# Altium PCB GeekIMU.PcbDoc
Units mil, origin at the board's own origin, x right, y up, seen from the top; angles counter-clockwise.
Board outline 1150.03 x 1090.03 mil, 2 copper layers (Top Layer, Bottom Layer); 40 components, 56 nets, 192 pads, 87 vias.
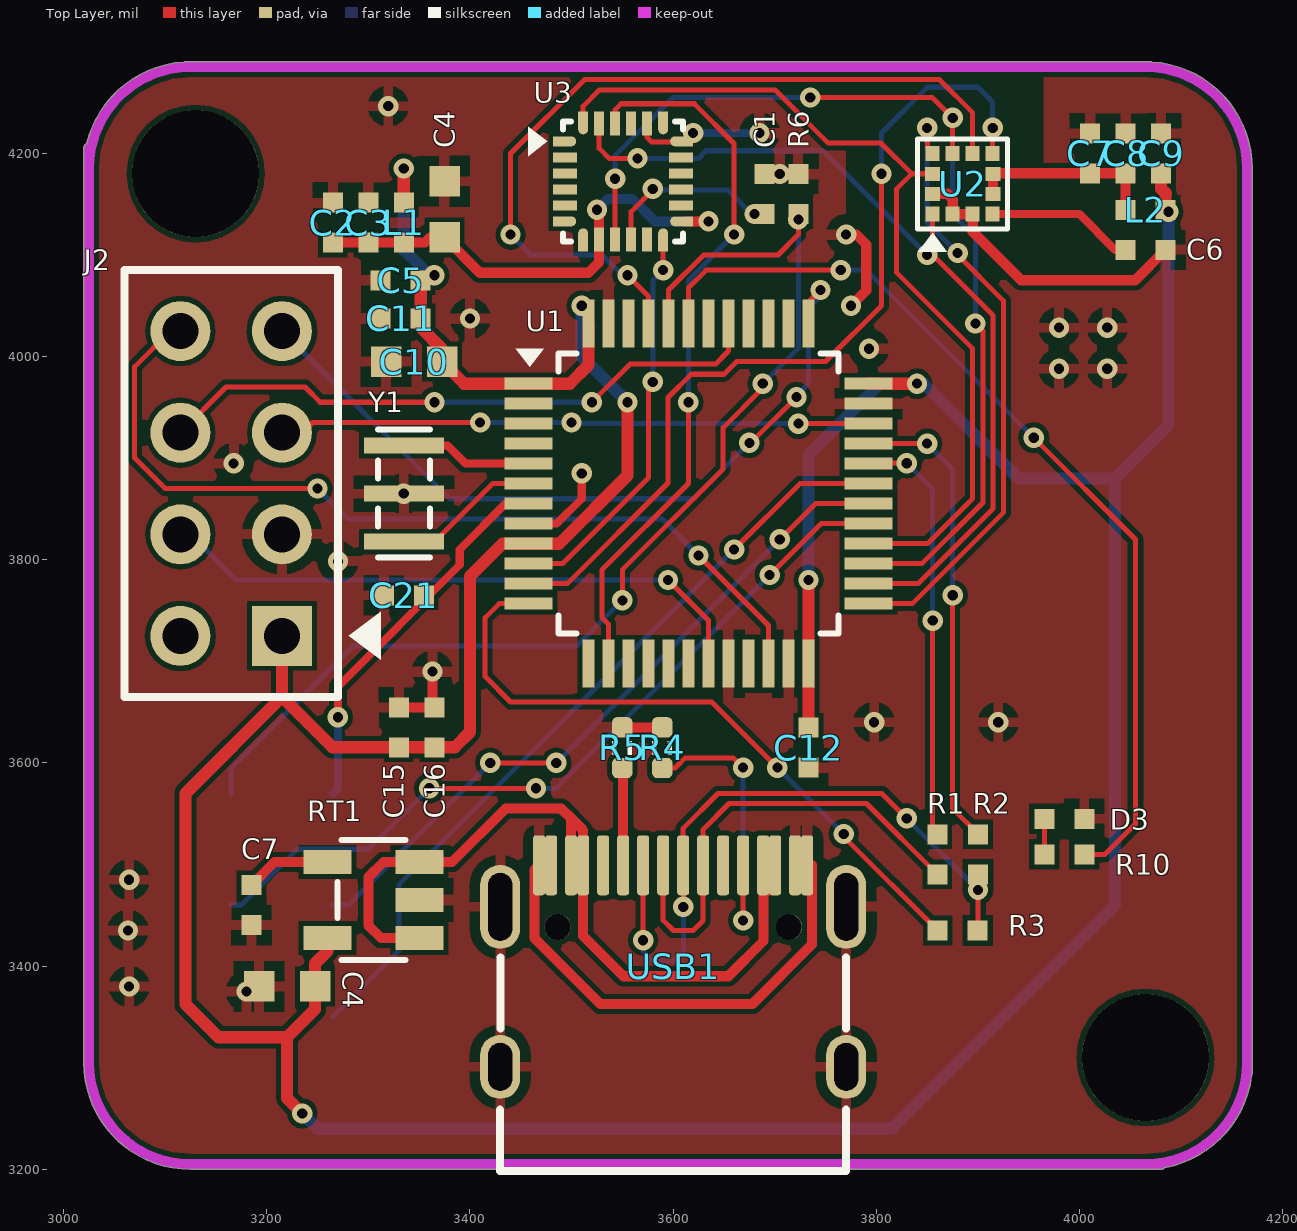
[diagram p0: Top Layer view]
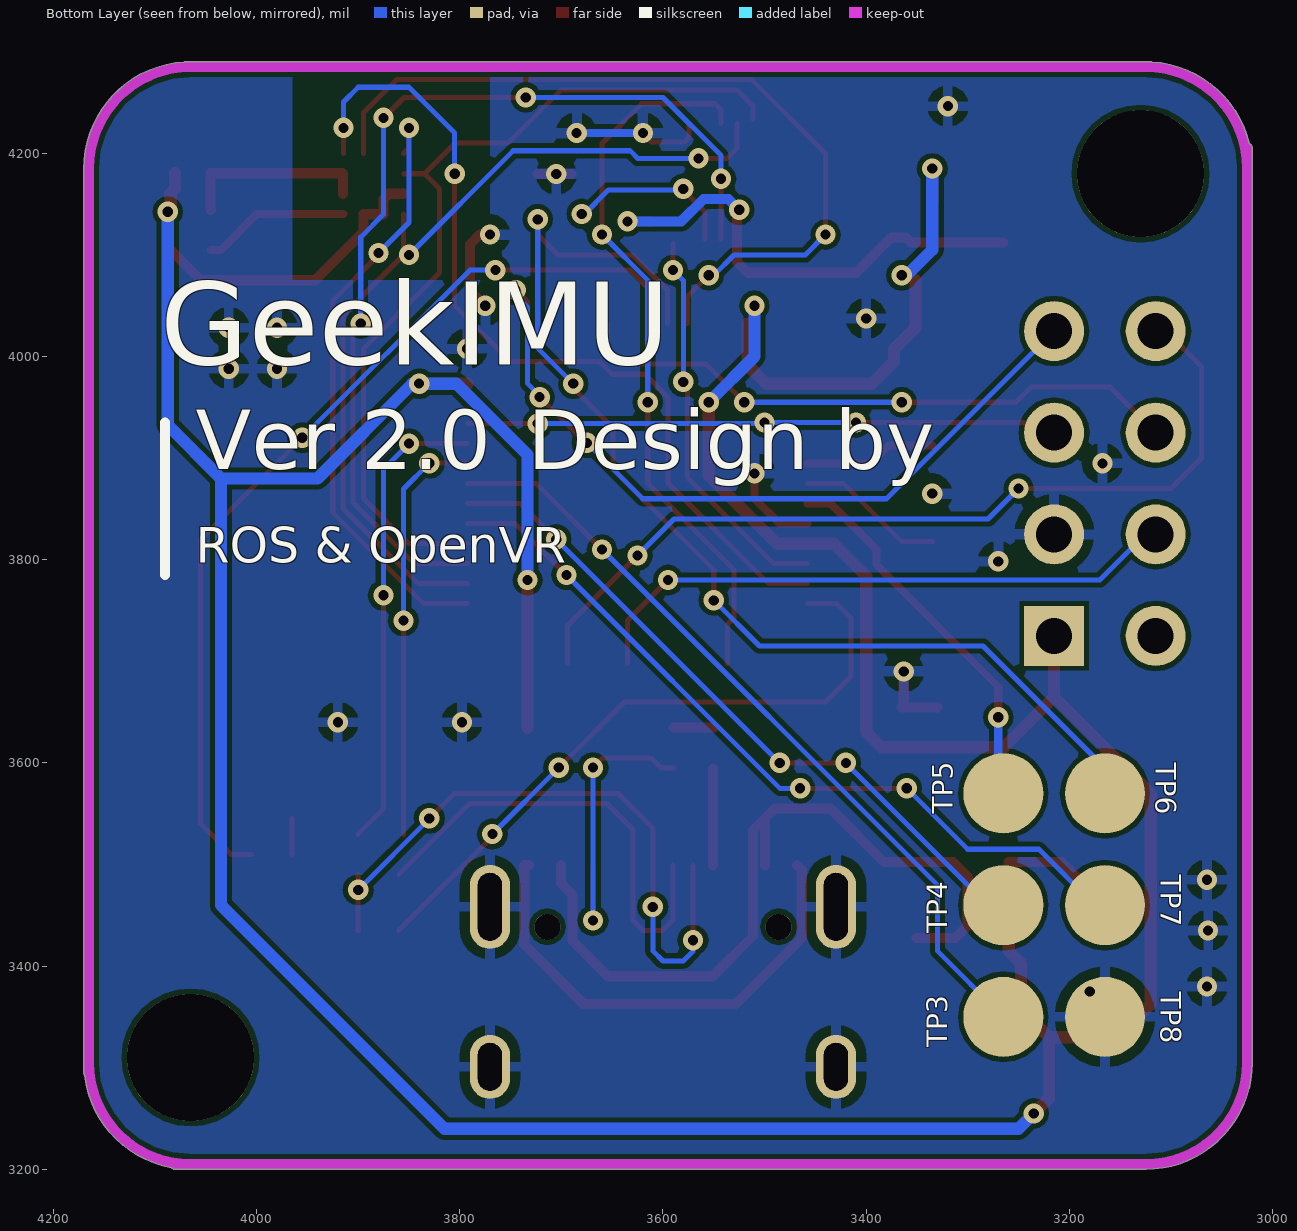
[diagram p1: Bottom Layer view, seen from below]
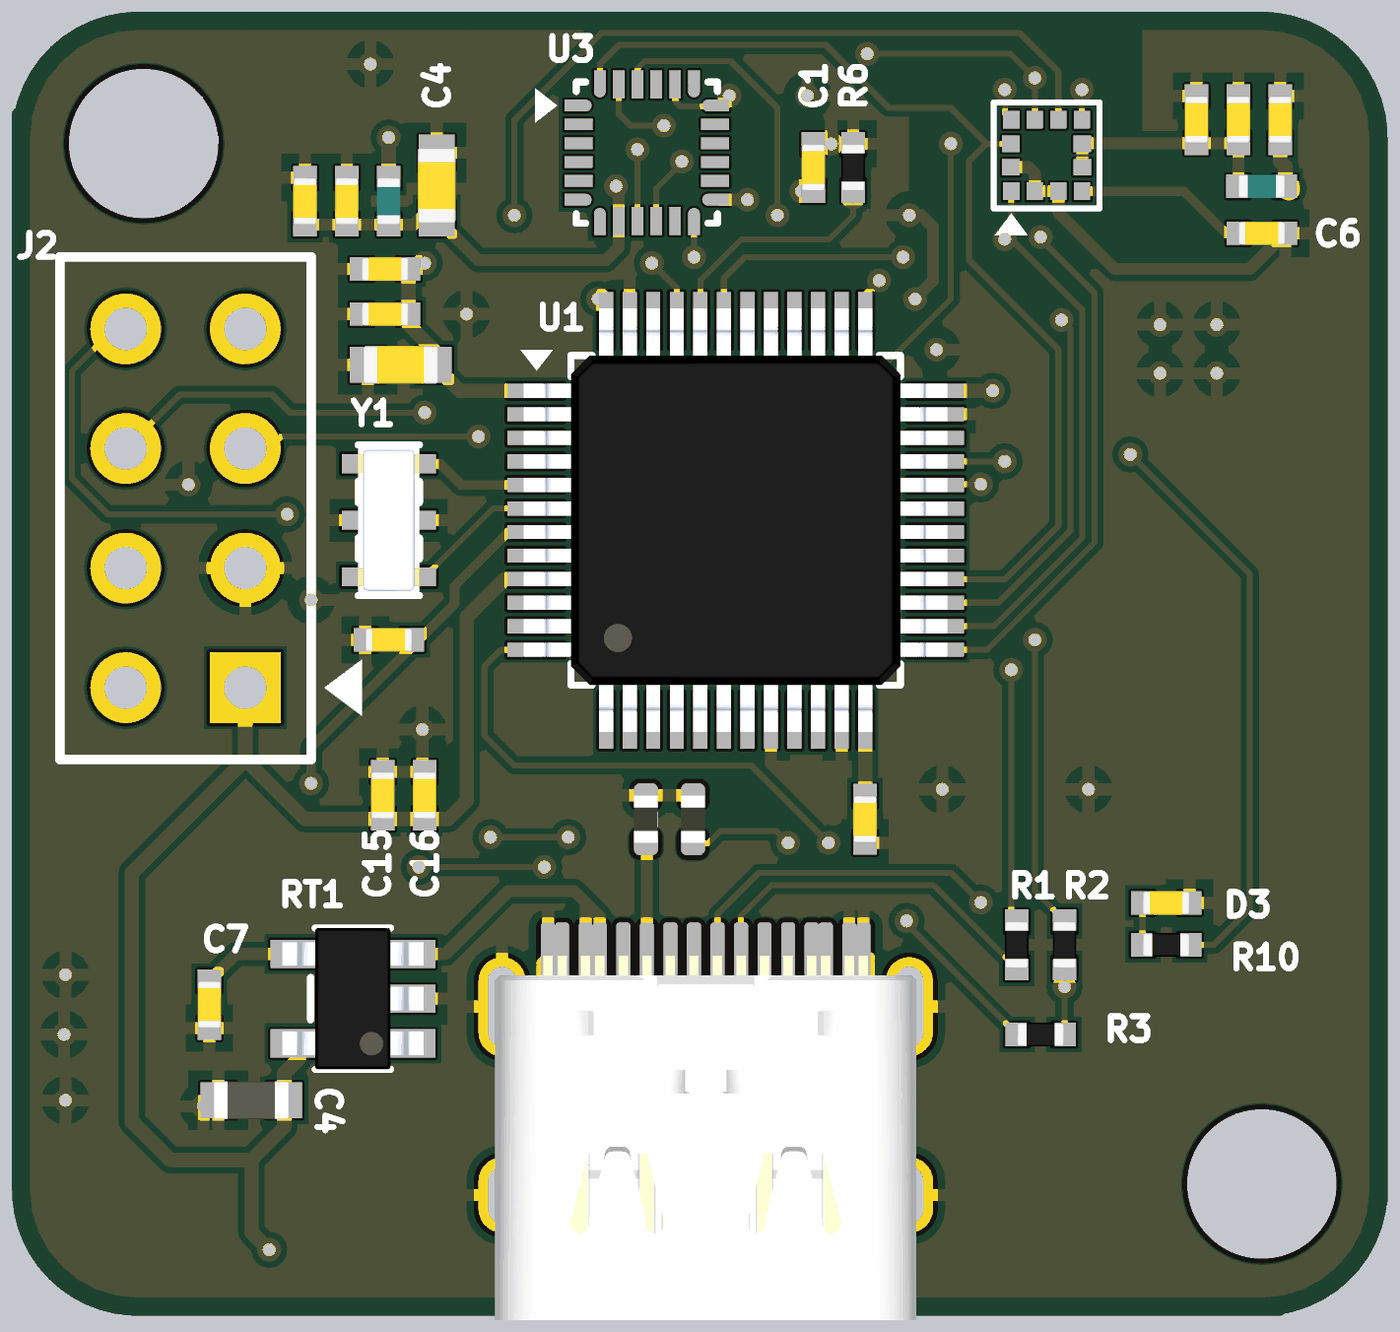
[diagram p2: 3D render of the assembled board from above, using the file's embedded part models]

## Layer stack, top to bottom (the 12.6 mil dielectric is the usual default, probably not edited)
Top Solder: solder mask 0.4, Solder Resist, Dk 3.5
Top Layer: signal copper 1.4
Dielectric1: dielectric 12.6, FR-4, Dk 4.8
Bottom Layer: signal copper 1.4
Bottom Solder: solder mask 0.4, Solder Resist, Dk 3.5

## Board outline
3019.99,3305 3019.99,4205 cw(c3025,4205) 3022.9,4209.55 cw(c3125,4185) 3118.62,4289.82 cw(c3120,4285) 3120,4290.02 4070,4290.02 cw(c4070,4285) 4071.38,4289.82 cw(c4065,4185) 4170.02,4185 4170.02,3295 cw(c4165,3295) 4169.25,3292.34 cw(c4065,3305) 4083.75,3201.67 cw(c4080,3205) 4080,3199.99 3125,3199.99 cw(c3125,3305)

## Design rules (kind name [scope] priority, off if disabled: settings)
Clearance [All] p1: gap=5 ignorepadtopadclearanceinfootprint=FALSE except(0: Arc-Hole Track-Hole SMDPad-Hole THPad-Hole Via-Hole Fill-Hole Poly-Hole Region-Hole Text-Hole)
DiffPairsRouting [All] p1: maxlimit=20 minlimit=5 mostfreqgap=5 toplayer_minwidth=15 toplayer_maxwidth=15 toplayer_prefwidth=15 bottomlayer_minwidth=15 bottomlayer_maxwidth=15 bottomlayer_prefwidth=15 maxuncoupledlength=500
FabricationTestpoint [(IsPad And (OnTopLayer Or OnBottomLayer))] p1: side=3 testpointundercomponent=TRUE minsize=40 maxsize=100 preferedsize=60 minholesize=0 maxholesize=40 preferedholesize=32 testpointgrid=1 allowsidetop=TRUE allowsidebottom=TRUE usegrid=TRUE gridtolerance=0.01
HoleSize [All] p1: absolutevalues=TRUE maxlimit=135 minlimit=1 maxpercent=80.000 minpercent=20.000
MinimumSolderMaskSliver [All] p1: minsoldermaskwidth=1
PolygonConnect [All] p1: connectstyle=Relief reliefconductorwidth=10 reliefentries=4 polygonreliefangle="90 Angle" airgapwidth=10
RoutingVias [All] p1: holewidth=8 width=18 viastyle="Through Hole" minholewidth=8 minwidth=8 maxholewidth=50 maxwidth=50
SilkToSilkClearance [All] p1: silktosilkclearance=0
SilkToSolderMaskClearance SilkscreenOverComponentPads [IsPad] p1: minsilkscreentomaskgap=0 clearancetoexposedcopper=TRUE
SolderMaskExpansion [All] p1: expansion=4
Width [All] p1: maxlimit=30 minlimit=5 preferedwidth=10 minimp=50.000000 maximp=50.000000 favimp=50.000000
24 further rules are at their usual default settings.

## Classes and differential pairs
component class MCU: C10 C11 C12 C15 C16 C21 D3 R6 R10 TP3 TP4 TP5 TP6 TP7 U1 Y1
component class Power: C4 C7 RT1
component class Sensor: C1 C2 C3 C4 C5 C6 C7 C8 C9 L1 L2 U2 U3
component class USB: R1 R2 R3 R4 R5 TP8 USB1

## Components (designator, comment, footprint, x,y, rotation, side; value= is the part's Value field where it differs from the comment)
C1 "0.1uF" CAP_CERAMIC_0402 3690,4160 r90 top
C2 "0.01uF" CAP_CERAMIC_0402 3265,4131.81 r90 top
C3 "0.1uF" CAP_CERAMIC_0402 3299.95,4131.81 r90 top
C4 "Cap" RESISTOR_0603 3220,3380 r0 top value=10uf
C4 "10uF" CAP_CERAMIC_0603 3375,4144.84 r90 top
C5 "0.1uF" CAP_CERAMIC_0402 3331.86,4075 r180 top
C6 "0.1uF" CAP_CERAMIC_0402 4065,4105 r0 top
C7 "Cap" CAP_CERAMIC_0402 3185,3460 r90 top value=0.1uf
C7 "0.1uF" CAP_CERAMIC_0402 4010.31,4200 r90 top
C8 "1uF" CAP_CERAMIC_0402 4045.31,4200 r90 top
C9 "0.1uF" CAP_CERAMIC_0402 4080.31,4200 r90 top
C10 "10uF" CAP_CERAMIC_0603 3345,3995 r180 top
C11 "0.1uF" CAP_CERAMIC_0402 3331.86,4037.42 r180 top
C12 "0.1uF" CAP_CERAMIC_0402 3733.27,3615 r270 top
C15 "1uF" CAP_CERAMIC_0402 3330,3635 r90 top
C16 "0.1uF" CAP_CERAMIC_0402 3365,3635 r90 top
C21 "0.1uF" CAP_CERAMIC_0402 3335,3765 r180 top
D3 "LED1" CAP_CERAMIC_0402 3985,3545 r0 top
J2 "4-103240-0-04" 4-103240-0-04 3215,3725 r90 top
L1 "MMZ1005S601C" INDUCTOR_0402 3334.89,4131.81 r90 top
L2 "MMZ1005S601C" INDUCTOR_0402 4064.84,4144.21 r0 top
R1 "22 ohm" RESISTOR_0402 3860,3510 r90 top
R2 "22 ohm" RESISTOR_0402 3900,3510 r90 top
R3 "1.5K" RESISTOR_0402 3880,3435 r180 top
R4 "5.1K" RES_0402 3589.37,3615 r90 top
R5 "5.1K" RES_0402 3550,3615 r270 top
R6 "10K" RESISTOR_0402 3723.23,4160 r270 top
R10 "" RESISTOR_0402 3985,3510 r0 top value=10K
RT1 "RT9193" SOT23-5L 3305,3465 r180 top
TP3 "TEST POINT" TEST_POINT_PAD 3265,3350 r0 bottom
TP4 "TEST POINT" TEST_POINT_PAD 3265,3460 r0 bottom
TP5 "TEST POINT" TEST_POINT_PAD 3265,3570 r0 bottom
TP6 "TEST POINT" TEST_POINT_PAD 3165,3570 r90 bottom
TP7 "TEST POINT" TEST_POINT_PAD 3165,3460 r90 bottom
TP8 "TEST POINT" TEST_POINT_PAD 3165,3350 r180 bottom
U1 "STM32F103C8T6" LQFP48 3625,3865 r0 top
U2 "LIS3MDL" LGA-12 3885,4170 r90 top
U3 "MPU-6500" QFN-24 3550.79,4172.4 r0 top
USB1 "Type-C" Type-C-TOP 3600,3400 r270 top
Y1 "CSTCE8M00G55-R0" CSTCE 3335,3865 r90 top

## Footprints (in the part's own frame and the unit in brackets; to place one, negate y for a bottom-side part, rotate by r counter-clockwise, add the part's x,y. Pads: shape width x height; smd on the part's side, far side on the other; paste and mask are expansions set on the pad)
4-103240-0-04 [mm]
  rect 1.5x1.5 hole 0.9 mask+0.076: 1(0,0)
  round 1.5 hole 0.9 mask+0.076: 2(0,2.54) 3(2.54,0) 4(2.54,2.54) 5(5.08,0) 6(5.08,2.54) 7(7.62,0) 8(7.62,2.54)
  silkscreen extent -1.52,-2.48 9.15,3.94
CAP_CERAMIC_0402 [mm]
  rect 0.5x0.5 smd mask+0.051: 1(-0.5,0) 2(0.5,0)
  body extent -0.5,-0.25 0.5,0.25, height 0.56
CAP_CERAMIC_0603 [mil]
  rect 30x30 smd mask+2: 1(-27.56,0) 2(27.56,0)
  body extent -31,-16 31,16, height 22
CSTCE [mm]
  rect 0.4x2 smd mask+0.064: 1(-1.2,0) 2(0,0) 3(1.2,0)
  silkscreen extent -1.6,-0.65 1.6,0.65, body extent -1.6,-0.65 1.6,0.65, height 0.7
INDUCTOR_0402 [mm]
  rect 0.5x0.5 smd mask+0.051: 1(-0.5,0) 2(0.5,0)
  body extent -0.5,-0.25 0.5,0.25, height 0.6
LGA-12 [mm]
  rect 0.375x0.35 smd mask+0.051: 1(-0.76,0.75) 2(-0.76,0.25) 3(-0.76,-0.25) 4(-0.76,-0.75) 7(0.76,-0.75) 8(0.76,-0.25) 9(0.76,0.25) 10(0.76,0.75)
  rect 0.35x0.375 smd mask+0.051: 5(-0.25,-0.76) 6(0.25,-0.76) 11(0.25,0.76) 12(-0.25,0.76)
  silkscreen extent -1.7,-1.12 1.13,1.13, body extent -1,-1 1,1, height 1
LQFP48 [mm]
  rect 1.2x0.3 smd mask+0.064: 1(-4.25,2.75) 2(-4.25,2.25) 3(-4.25,1.75) 4(-4.25,1.25) 5(-4.25,0.75) 6(-4.25,0.25) 7(-4.25,-0.25) 8(-4.25,-0.75) 9(-4.25,-1.25) 10(-4.25,-1.75) 11(-4.25,-2.25) 12(-4.25,-2.75) 25(4.25,-2.75) 26(4.25,-2.25) 27(4.25,-1.75) 28(4.25,-1.25) 29(4.25,-0.75) 30(4.25,-0.25) 31(4.25,0.25) 32(4.25,0.75) 33(4.25,1.25) 34(4.25,1.75) 35(4.25,2.25) 36(4.25,2.75)
  rect 0.3x1.2 smd mask+0.064: 13(-2.75,-4.25) 14(-2.25,-4.25) 15(-1.75,-4.25) 16(-1.25,-4.25) 17(-0.75,-4.25) 18(-0.25,-4.25) 19(0.25,-4.25) 20(0.75,-4.25) 21(1.25,-4.25) 22(1.75,-4.25) 23(2.25,-4.25) 24(2.75,-4.25) 37(2.75,4.25) 38(2.25,4.25) 39(1.75,4.25) 40(1.25,4.25) 41(0.75,4.25) 42(0.25,4.25) 43(-0.25,4.25) 44(-0.75,4.25) 45(-1.25,4.25) 46(-1.75,4.25) 47(-2.25,4.25) 48(-2.75,4.25)
  silkscreen extent -4.58,-3.5 3.5,3.62, body extent -4.5,-4.5 4.5,4.5, height 1.5
QFN-24 [mm]
  rect 0.4x0.25 smd mask+0.05: 1(-1.55,1) 6(-1.55,-1) 13(1.55,-1) 18(1.55,1)
  rrect100% 0.35x0.25 smd mask+0.05: 1(-1.35,1) 6(-1.35,-1) 13(1.35,-1) 18(1.35,1)
  rect 0.6x0.25 smd mask+0.05: 2(-1.45,0.6) 3(-1.45,0.2) 4(-1.45,-0.2) 5(-1.45,-0.6) 14(1.45,-0.6) 15(1.45,-0.2) 16(1.45,0.2) 17(1.45,0.6)
  rect 0.25x0.4 smd mask+0.05: 7(-1,-1.55) 12(1,-1.55) 19(1,1.55) 24(-1,1.55)
  rrect100% 0.25x0.35 smd mask+0.05: 7(-1,-1.35) 12(1,-1.35) 19(1,1.35) 24(-1,1.35)
  rect 0.25x0.6 smd mask+0.05: 8(-0.6,-1.45) 9(-0.2,-1.45) 10(0.2,-1.45) 11(0.6,-1.45) 20(0.6,1.45) 21(0.2,1.45) 22(-0.2,1.45) 23(-0.6,1.45)
  silkscreen extent -2.37,-1.5 1.5,1.5, body extent -1.5,-1.5 1.5,1.5, height 0.9
RES_0402 [mil]
  rrect50% 20x20 smd: 1(-20,0) 2(20,0)
  silkscreen extent -7,-10 7,10, body extent -20,-10 20,10, height 14
RESISTOR_0402 [mm]
  rect 0.5x0.5 smd mask+0.051: 1(-0.5,0) 2(0.5,0)
  body extent -0.5,-0.25 0.5,0.25, height 0.38
RESISTOR_0603 [mil]
  rect 30x30 smd mask+2: 1(-27.56,0) 2(27.56,0)
  body extent -32,-16 31,16, height 20
SOT23-5L [mm]
  rect 1.2x0.6 smd mask+0.051: 1(-1.15,0.95) 2(-1.15,0) 3(-1.15,-0.95) 4(1.15,-0.95) 5(1.15,0.95)
  silkscreen extent -0.8,-1.5 0.9,1.5, body extent -1.5,-1.5 1.5,1.5, height 1.3
TEST_POINT_PAD [mm]
  round 2 smd mask+0.064: 1(0,0)
Type-C-TOP [mm]
  round 0.65 hole 0.65: 0(-0.98,2.89) 0(-0.98,-2.89)
  oval 1.6x1 hole 0.6 slot 1.2 at 0 deg: 1(2.52,4.325) 2(2.52,-4.325)
  oval 2.1x1 hole 0.6 slot 1.7 at 0 deg: 3(-1.48,-4.325) 4(-1.48,4.325)
  rrect50% 1.5x0.3 smd: A1(-2.52,-3.35) A4(-2.52,-2.55) A5(-2.52,-1.25) A6(-2.52,-0.25) A7(-2.52,0.25) A8(-2.52,1.25) A9(-2.52,2.55) A12(-2.52,3.35) B1(-2.52,3.05) B4(-2.52,2.25) B5(-2.52,1.75) B6(-2.52,0.75) B7(-2.52,-0.75) B8(-2.52,-1.75) B9(-2.52,-2.25) B12(-2.52,-3.05)
  silkscreen extent -0.22,-4.33 5.12,4.33, body extent -2.57,-4.48 5.18,4.47, height 3.26

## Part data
C1 C3 C5 C6 C7 C9 C11 C12 C16 C21: library part "CAP, CERAMIC", "CAP, CERAMIC, 0.1uF, ?0%, 16V, X7R, 0402", Dielectric=X7R, Manufacturer="MURATA ELECTRONICS", Package=0402, Part Number=GRM155R71C104KA88D, Tolerance=?0%, Voltage=16V
C2: library part "CAP, CERAMIC", "CAP, CERAMIC, 0.01uF, ?0%, 25V, X7R, 0402", Dielectric=X7R, Manufacturer="MURATA ELECTRONICS", Package=0402, Part Number=GRM155R71E103KA01D, Tolerance=?0%, Voltage=25V
C4 C7: "Capacitor"
C4 C10: library part "CAP, CERAMIC", "CAP, CERAMIC, 10uF, ?0%, 6.3V, X5R, 0603", Dielectric=X5R, Manufacturer="MURATA ELECTRONICS", Package=0603, Part Number=GRM188R60J106ME47D, Tolerance=?0%, Voltage=6.3V
C8 C15: library part "CAP, CERAMIC", "CAP, CERAMIC, 1uF, ?0%, 10V, X5R, 0402", Dielectric=X5R, Manufacturer="MURATA ELECTRONICS", Package=0402, Part Number=GRM155R61A105KE15D, Tolerance=?0%, Voltage=10V
D3: "Typical RED GaAs LED"
J2: "CONNECTOR, HEADER, 2X4, 0.1\" PITCH", Manufacturer="TE CONNECTIVITY"
L1 L2: library part INDUCTOR, "FERRITE CHIP BEAD, 600 OHM @ 100MHz, 300mA, 0402", Manufacturer="TDK CORPORATION", Package=0402
R1 R2: library part RESISTOR, "RES, 22 OHM, 1/10W, ?%, 0402", Manufacturer=PANASONIC, Package=0402, Part Number=ERJ-2RKF22R0X, Power Rating=1/10W, Tolerance=?%
R3: library part RESISTOR, "RES, 1.5K OHM, 1/10W, ?%, 0402", Manufacturer=PANASONIC, Package=0402, Part Number=ERJ-2RKF1501X, Power Rating=1/10W, Tolerance=?%
R4: library part RESISTOR, "RES, 1.5K OHM, 1/10W, ?%, 0402", Manufacturer=PANASONIC, Package=0402, Part Number=ERJ-2RKF1501X, Power Rating=1/10W, Tolerance=10%
R5: library part RESISTOR, "RES, 1.5K OHM, 1/10W, ?%, 0402", Manufacturer=PANASONIC, Package=0402, Part Number=ERJ-2RKF1501X, Power Rating=1/10W
R6: library part RESISTOR, "RES, 10K OHM, 1/10W, ?%, 0402", Manufacturer=PANASONIC, Package=0402, Part Number=ERJ-2RKF1002X, Power Rating=1/10W, Tolerance=?%
R10: library part Res2, "Resistor"
RT1: "Power"
TP3 TP4 TP5 TP6 TP7 TP8: library part TEST_POINT
U1: "IC, STM32 MICROCONTROLLER, ARM CORTEX M3", Manufacturer="ST MICROELECTRONICS"
U2: "IC, MEMS 3 AXIS MAGNETOMETER", Manufacturer=STMICROELECTRONICS, Part Number=LIS3MDLTR
U3: "IC, MEMS 3 AXIS GYROSCOPE AND 3 AXIS ACCELEROMETER", Manufacturer=INVENSENSE
USB1: library part USB-Type-C-TOP-16P, "16脚USB TypeC"
Y1: "CERAMIC RESONATOR, 8MHz, +/-0.2%, 33pF, SMD", Manufacturer="MURATA ELECTRONICS"

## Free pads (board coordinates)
  round 125 hole 125 unplated: 0(3130,4180) 0(4065,3310)

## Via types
v1: diameter 20/20 (per signal layer), hole 10, Top Layer to Bottom Layer, tented both sides, 87 vias

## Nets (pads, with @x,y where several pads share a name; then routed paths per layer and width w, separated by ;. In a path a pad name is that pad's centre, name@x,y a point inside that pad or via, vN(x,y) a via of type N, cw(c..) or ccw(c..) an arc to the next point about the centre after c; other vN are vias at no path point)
3.3V: C4.2@3247.56,3380 C5.1 C9.1 C10.1 C11.1 C12.1 C15.1 C16.1 J2.1 L1.2 L2.2 RT1.5 U1.1 U1.9 U1.24 U1.36 U1.48 | length 4217
  Top Layer w12: J2.1 3215,3665 ; v1(3235,3255) 3220,3270 3220,3330 ; RT1.5 3259.72,3414.72 3247.56,3402.56 3247.56,3380 3247.56,3357.56 3220,3330 ; L1.2 3334.9,4175 ; C5.1 C11.1 3351.55,4028.45 3372.56,4007.44 C10.1 3394.29,3973.27 U1.1 3498.27,3973.27 3516.73,3991.73 U1.48 ; v1(3555,3955) 3555,3882.99 3487.79,3815.79 U1.9 3432,3815.79 3400,3783.79 3400,3630.32 3385,3615.32 C16.1 C15.1 3264.68,3615.32 3215,3665 ; C12.1 U1.24 v1(3733.27,3780) ; U1.36 v1(3840,3973.27) ; C9.1 4080.31,4165 4085,4160.31 4084.53,4159.84 L2.2 ; 3215,3665 3120,3570 3120,3362.56 3152.56,3330 3220,3330
  Bottom Layer w12: v1(3235,3255) 3250,3240 3815,3240 4035,3460 4035,3880 ; v1(3334.9,4185) 3334.9,4105.1 3360,4080 v1(3365,4080) ; v1(3510,4050) 3510,4000 v1(3555,3955) ; v1(3733.27,3780) 3733.27,3903.27 3803.27,3973.27 v1(3840,3973.27) 3846.73,3973.27 3940,3880 4035,3880 ; v1(4087.5,4142.5) 4087.5,3932.5 4035,3880
AUX_CL: U3.7
AUX_DA: U3.21
BOOT0: R6.2 TP6.1 U1.44 | length 1128.9
  Top Layer w5: v1(3550,3760) 3550,3790 3649.21,3889.21 3649.21,3930 3688.27,3969.05 v1(3688.27,3973.27) ; U1.44 3595.47,4065.47 3630,4100 3703.23,4100 3723.23,4120 v1(3723.23,4135) R6.2
  Bottom Layer w5: TP6.1 3165,3595 3285,3715 3505,3715 v1(3550,3760) ; v1(3688.27,3973.27) 3723.23,4008.23 v1(3723.23,4135)
D+: R1.1 USB1.A6 USB1.B6 | length 461.3
  Top Layer w5: USB1.A6 3590.16,3445.16 3600.31,3435 3619.68,3435 3629.53,3444.84 USB1.B6 3629.53,3534.53 3655,3560 3790.25,3560 3859.94,3490.32 R1.1
D-: R2.1 R3.1 USB1.A7 USB1.B7 | length 652.4
  Top Layer w5: v1(3570.47,3425.47) USB1.B7 ; v1(3610,3458.27) 3610,3499.05 USB1.A7 3609.84,3535.63 3644.21,3570 3805.39,3570 v1(3830,3545.39) ; R3.1 3900,3435.32 v1(3900,3475) R2.1
  Bottom Layer w5: v1(3570.47,3425.47) 3570.47,3414.53 3580,3405 3600,3405 3610,3415 v1(3610,3458.27) ; v1(3830,3545.39) 3830,3545 v1(3900,3475)
FSYNC: U3.11
GND: C1.2 C2.2 C3.2 C4.1@3192.44,3380 C4.2@3375,4172.4 C5.2 C6.2 C7.1@3185,3440.32 C7.2@4010.31,4219.69 C8.2 C9.2 C10.2 C11.2 C12.2 C15.2 C16.2 C21.2 D3.2 J2.3 R4.2 R5.1 R6.1 RT1.2 TP8.1 U1.8 U1.20 U1.23 U1.35 U1.47 U2.2 U2.3 U2.12 U3.18 U3.20 USB1.1 USB1.2 USB1.3 USB1.4 USB1.A1 USB1.A12 USB1.B1 USB1.B12 Y1.2 | length 1217.2
  Top Layer w5: U3.20 3574.41,4215.59 3578.84,4211.16 3611.81,4211.16 U3.18@3611.81,4211.77
  Top Layer w8: U1.8 3485.47,3835.47 3510,3860 v1(3510,3885)
  Top Layer w10: C15.2 C16.2 3363.07,3656.61 v1(3363.07,3690) ; USB1.A1 3463.43,3494.53 3463.43,3427.68 3528.54,3362.56 3677.95,3362.56 3736.57,3421.18 3736.57,3499.21 USB1.A12 ; R5.1 R4.2 ; C1.2 R6.1 ; v1(3770.28,4120) 3780.25,4120 3790,4110.25 3790,4065 v1(3775,4050) ; U2.12 3869.84,4160.16 3875.16,4154.84 U2.2 U2.3 3894.84,4122.66 3942.5,4075 4054.68,4075 C6.2
  Bottom Layer w8: v1(3619.68,4220) v1(3685,4220)
  other v1: 3180,3375 3064.59,3380 3063.48,3435 3064.59,3485 3797.82,3640 3920,3640 3270.09,3798.36 3334.9,3865 3167.44,3894.84 3979.84,3987.94 4027.32,3987.94 3792.8,4007.66 3979.84,4028.45 4027.32,4028.45 3400,4037.42 3705,4179.69 3319.6,4246.42
GYRO_CS: U1.14 U3.22 | length 717.7
  Top Layer w5: U1.14 3536.42,3736.46 3530,3742.88 3530,3790 3615,3875 v1(3615,3955) ; U3.22 3542.91,4242.91 3548.8,4248.8 3620.89,4248.8 3660,4209.69 v1(3660,4120)
  Bottom Layer w5: v1(3615,3955) 3615,4075 v1(3660,4120)
GYRO_IRQ: U1.10 U3.12 | length 389.7
  Top Layer w5: U1.10 3491.1,3796.1 3575.79,3880.79 3575.79,3970.79 v1(3580,3975) ; v1(3590.16,4085) U3.12@3590.16,4111.38
  Bottom Layer w5: v1(3580,3975) 3580,4074.84 v1(3590.16,4085)
ICLK: U1.21
IDATA: J2.8 U1.22 | length 879.2
  Top Layer w5: J2.8 3105,4025 3070,3990 3070,3900 3100,3870 v1(3250,3870) ; v1(3625,3804.21) 3693.9,3735.31 U1.22
  Bottom Layer w5: v1(3250,3870) 3280,3840 3589.21,3840 v1(3625,3804.21)
IO0: U1.18
IO1: J2.4 U1.19 | length 597.5
  Top Layer w5: v1(3595,3780) 3634.84,3740.16 U1.19
  Bottom Layer w5: J2.4 3125,3825 3170,3780 v1(3595,3780)
IO3: U1.40
IO4: J2.6 U1.41 | length 612.2
  Top Layer w5: J2.6 3160,3970 3237.56,3970 3252.56,3955 v1(3365.04,3955) ; v1(3520,3955) 3557.5,3992.5 3641.71,3992.5 3654.53,4005.32 U1.41
  Bottom Layer w5: v1(3365.04,3955) v1(3520,3955)
LIS3MDL_VDDIO: C7.1@4010.31,4180.32 C8.1 L2.1 U2.5 U2.6 | length 186.4
  Top Layer w10: U2.5 U2.6 3915.39,4180.32 4010.31,4180.32 C8.1 4045.31,4144.37 L2.1
MAG_CS: U1.25 U2.10 | length 606.9
  Top Layer w5: U1.25 3835.4,3756.73 3925,3846.33 3925,4055 3880,4100 v1(3880,4101.85) ; v1(3850,4225) 3850.31,4224.69 3850.31,4205.08 U2.10
  Bottom Layer w5: v1(3850,4225) 3850,4131.85 v1(3880,4101.85)
MAG_DRDY: U1.45 U2.8 | length 806.1
  Top Layer w5: v1(3440,4120) 3440,4199.84 3512.66,4272.5 3862.25,4272.5 3894.84,4239.91 U2.8 ; v1(3555,4080) 3575.79,4059.21 U1.45
  Bottom Layer w5: v1(3440,4120) 3460,4100 3530,4100 3550,4080 v1(3555,4080)
MAG_IRQ: U1.11 U2.7 | length 864.7
  Top Layer w5: U1.11 3495.82,3776.42 3595,3875.59 3595,3959.75 3617.75,3982.5 3650,3982.5 3662.5,3995 3750,3995 3805,4050 v1(3805,4179.92) ; U2.7 v1(3914.53,4225)
  Bottom Layer w5: v1(3805,4179.92) 3805,4220 3850,4265 3900,4265 3914.53,4250.47 v1(3914.53,4225)
MAG_SOC: U1.46
MEMS_MISO: U1.27 U2.9 U3.9 | length 1010.4
  Top Layer w5: U3.9 v1(3542.91,4175) ; v1(3735,4255) 3855,4255 v1(3875.16,4234.84) U2.9 ; U1.27 3844.77,3796.1 3905,3856.33 3905,4025 v1(3897.5,4032.5)
  Bottom Layer w5: v1(3542.91,4175) 3542.91,4197.99 3599.92,4255 v1(3735,4255) ; v1(3875.16,4234.84) 3875.16,4140.16 3875,4140 3897.5,4117.5 v1(3897.5,4032.5)
MEMS_MOSI: U1.28 U2.11 U3.24 | length 875.2
  Top Layer w5: U3.24@3511.42,4233.43 3511.42,4246.42 3527.5,4262.5 3700.26,4262.5 3752.76,4210 3804.68,4210 3834.84,4179.84 ; U1.28 3850.31,3815.79 3894.84,3860.32 3894.84,4007.66 3820,4082.5 3820,4165 3834.84,4179.84 ; U2.11 3834.84,4179.84
MEMS_SCK: U1.26 U2.1 U3.23 | length 873.2
  Top Layer w5: U3.23 3527.17,4205 3537.17,4195 v1(3565,4195) ; U1.26 3840.95,3776.42 3915,3850.47 3915,4040.47 v1@3855.47,4100 ; v1(3850,4100) v1@3855.47,4100 ; U2.1 v1@3855.47,4100
  Bottom Layer w5: v1@3567.18,4197.19 v1(3565,4195) 3624.84,4195 3632.34,4202.5 3747.5,4202.5 v1(3850,4100)
MPU6500_VDDIO: C2.1 C3.1 C4.1@3375,4117.28 L1.1 U3.8 U3.13 | length 481.7
  Top Layer w10: C2.1 C3.1 L1.1 3355.75,4112.13 3360.91,4117.28 3375,4117.28 3409.78,4082.5 3516.73,4082.5 3527.17,4092.93 U3.8 3527.17,4142.2 v1(3525,4144.37) ; U3.13@3611.81,4133.03 v1(3634.84,4133.03)
  Bottom Layer w10: v1(3525,4144.37) 3535.63,4155 3560,4155 3581.97,4133.03 v1(3634.84,4133.03)
NC1: U3.1
NC2: U3.2
NC3: U3.3
NC4: U3.4
NC5: U3.5
NC6: U3.6
NC7: U3.14
NC8: U3.15
NC9: U3.16
NC10: U3.17
NetC1_1: C1.1 U3.10 | length 169.5
  Top Layer w5: U3.10 3558.66,4142.44 3580,4163.78 v1(3580,4165)
  Bottom Layer w5: v1(3580,4165) 3580,4163.78 3653.78,4163.78 3677.24,4140.31 v1(3680,4140.31)
NetC6_1: C6.1 U2.4 | length 145.3
  Top Layer w8: U2.4 3999.92,4140.08 4035,4105 C6.1
NetC7_2: C7.2@3185,3479.69 RT1.4 | length 84.1
  Top Layer w10: C7.2@3185,3479.69 3207.72,3502.4 RT1.4
NetD3_1: D3.1 R10.1 | length 35
  Top Layer w5: R10.1 D3.1
NetR4_1: R4.1 USB1.B5 | length 292.5
  Top Layer w5: R4.1 3601.81,3595 3611.81,3605 3659.21,3605 v1(3668.9,3595.31) ; v1(3668.9,3444.84) USB1.B5
  Bottom Layer w5: v1(3668.9,3444.84) v1(3668.9,3595.31)
NetR5_2: R5.2 USB1.A5 | length 96.1
  Top Layer w5: R5.2 R5.2@3550.79,3594.21
  Top Layer w10: USB1.A5 R5.2@3550.79,3594.21
NRST: C21.1 TP5.1 U1.7 | length 378.3
  Top Layer w8: v1(3270,3645) 3270,3675 3390,3795 3390,3810.22 3434.94,3855.16 U1.7
  Bottom Layer w8: TP5.1 3270,3575 v1(3270,3645)
OSC_IN: U1.5 Y1.3 | length 130
  Top Layer w8: Y1.3 3377.75,3912.25 3395.47,3894.53 U1.5
OSC_OUT: U1.6 Y1.1 | length 146.3
  Top Layer w5: Y1.1 3365.04,3817.76 3422.12,3874.84 U1.6
RESV: U3.19
RUN_STATE: R10.2 U1.43 | length 934.9
  Top Layer w5: U1.43 3615.16,4067.66 3632.5,4085 v1(3765,4085) ; v1(3955,3920) 4055,3820 4055,3540 4025,3510 R10.2
  Bottom Layer w5: v1(3765,4085) 3790,4085 v1(3955,3920)
RX: TP3.1 U1.31 | length 782.8
  Top Layer w5: v1(3660,3810) 3724.84,3874.84 U1.31
  Bottom Layer w5: TP3.1 3330,3415 3330,3480 v1(3660,3810)
SWCLK: J2.7 U1.37 | length 769.4
  Top Layer w5: v1(3675,3915) 3676.42,3915 v1(3721.42,3960) ; U1.37 3733.27,4053.74 v1(3745,4065.47)
  Bottom Layer w5: J2.7 3380,3860 3620,3860 v1(3675,3915) ; v1(3721.42,3960) 3721.42,3961.49 3733.23,3973.31 3733.23,4048.23 3745,4060 v1(3745,4065.47)
SWDIO: J2.5 U1.34 | length 581.9
  Top Layer w5: J2.5 3235,3925 3245,3935 v1(3410,3935) ; v1(3723.23,3933.9) U1.34
  Bottom Layer w5: v1(3410,3935) v1(3500,3935) 3501.1,3933.9 v1(3723.23,3933.9)
SWO: U1.39
TX: TP4.1 U1.30 | length 691
  Top Layer w5: v1(3420,3600) v1(3485,3600) ; v1(3705,3820) 3740.16,3855.16 U1.30
  Bottom Layer w5: TP4.1 3280,3460 v1(3420,3600) ; v1(3485,3600) v1(3705,3820)
UARTEN: TP7.1 U1.29 | length 782.8
  Top Layer w5: v1(3360,3575) v1(3465,3575) ; v1(3695,3785) 3745.47,3835.47 U1.29
  Bottom Layer w5: TP7.1 3175,3460 3230,3515 3300,3515 v1(3360,3575) ; v1(3465,3575) 3485,3575 v1(3695,3785)
USBDM: R1.2 U1.32 | length 413.7
  Top Layer w5: U1.32 3792.8,3895 v1(3830,3895) ; R1.2@3855.47,3529.68 v1(3855.47,3740)
  Bottom Layer w5: v1(3830,3895) 3855.47,3869.53 v1(3855.47,3740)
USBDP: R2.2 U1.33 | length 462.9
  Top Layer w5: U1.33 v1(3850,3914.21) ; v1(3875.16,3765) 3875.16,3555 3900,3530.16 R2.2
  Bottom Layer w5: v1(3850,3914.21) 3875.16,3889.05 v1(3875.16,3765)
USBDP_PU: R3.2 U1.12 | length 656.7
  Top Layer w5: U1.12 3428.86,3756.73 3415,3742.88 3415,3685 3440,3660 3637.91,3660 v1(3702.6,3595.31) ; v1(3767.91,3530) 3767.91,3527.4 R3.2
  Bottom Layer w5: v1(3702.6,3595.31) v1(3767.91,3530)
VCC: RT1.1 RT1.3 USB1.A4 USB1.A9 USB1.B4 USB1.B9 | length 788.8
  Top Layer w10: RT1.1 3312.4,3427.6 3300,3440 3300,3487.56 3314.84,3502.4 RT1.3 3382.4,3502.4 3435,3555 3490,3555 3499.61,3545.39 ; USB1.A4 3499.61,3545.39 ; USB1.A9 3700.39,3481.5 3688.9,3470 3688.9,3424.69 3654.21,3390 3551.1,3390 3511.42,3429.68 USB1.B9 3511.42,3533.58 3499.61,3545.39
pads on no net: J2.2 U1.2 U1.3 U1.4 U1.13 U1.15 U1.16 U1.17 U1.38 U1.42 USB1.0 USB1.A8 USB1.B8

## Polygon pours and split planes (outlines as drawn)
GND on Bottom Layer "Bottom Layer-GND" (solid, pour order 1007): 3110,4285 3770,4285 3770,4080 3775,4075 3965,4075 3965,4280 3970,4285 4085,4285 4095,4280 4100,4280 4110,4280 4155,4235 4160,4215 4165,4205 4165,3275 4150,3260 4150,3245 4145,3245 4110,3210 3095,3210 3090,3215 3075,3215 3040,3250 3040,3255 3030,3265 3030,3285 3025,3290 3025,4210 3035,4220 3035,4235 3075,4275 3085,4275
GND on Top Layer "Top Layer-GND" (solid, pour order 1011): 3135,4285 3770,4285 3770,4075.28 3770.28,4075 3965,4075 3965,4285 4100,4285 4120,4265 4130,4265 4155,4240 4155,4216.77 4160,4211.77 4155,4206.77 4155,3255 4125,3225 4120,3225 4100,3205 3100,3205 3090,3215 3075,3215 3035,3255 3035,3270 3025,3280 3025,4210 3035,4220 3035,4240 3050,4255 3050,4250 3080,4280 3090,4280

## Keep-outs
Keep-Out Layer:
  lines w10: 3025,4185 cw(c3125,4185) 3125,4285 ; 3025,4205 3025,3305 ccw(c3125,3305) 3125,3205 4080,3205 ; 3120,4285 4070,4285 ; 4065,3205 ccw(c4065,3305) 4165,3305 ; 4065,4285 cw(c4065,4185) 4165,4185 4165,3295

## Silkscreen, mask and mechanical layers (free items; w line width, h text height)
Bottom Overlay:
  lines w10: 4090,3785 4090,3935
  text "GeekIMU" at 4095,3965 h140
  text "Design by" at 3733.27,3870 h100
  text "Ver 2.0" at 4060,3870 h100
  text "ROS & OpenVR" at 4060,3785 h60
